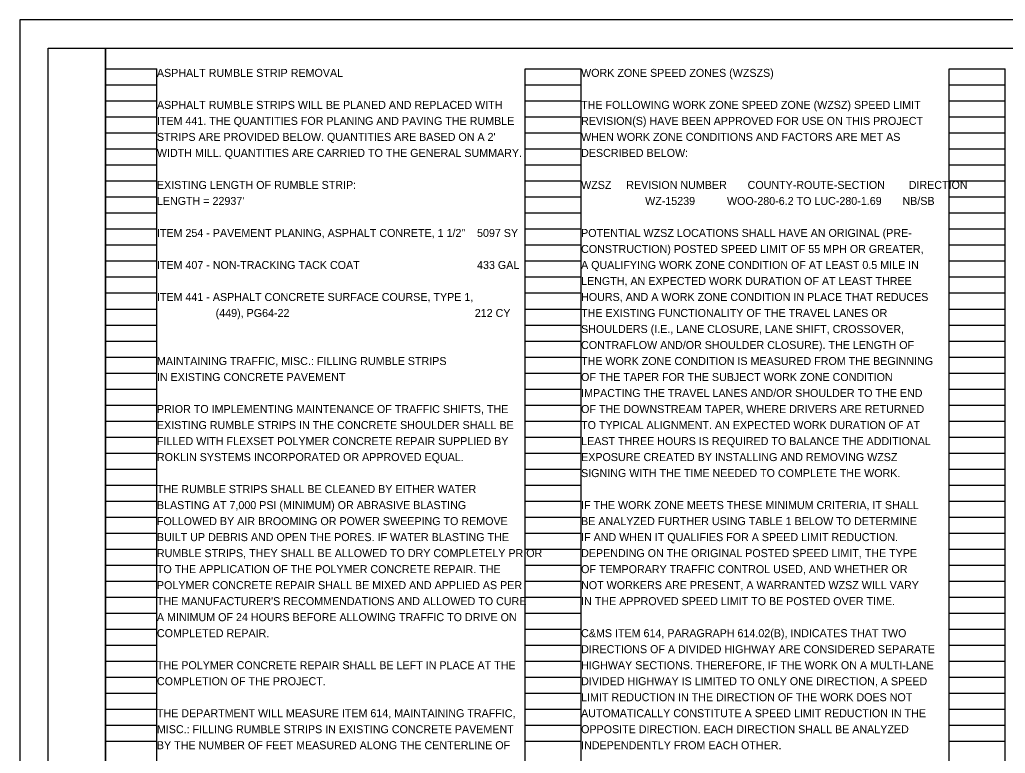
# Model space of a CAD drawing. Extents: x 0 to 34, y -3.9 to 22.
# Drawn here: x 0 to 17.24, y 9.17 to 22 of the extents above; entities that cross this region are included whole.
import ezdxf

# ---------------------------------------------------------------- set-up
doc = ezdxf.new("R2010")
doc.units = 0
for name, color, linetype in [('SH_Border', 7, 'Continuous'), ('SH_Cut_Line', 7, 'Continuous'), ('SH_Data', 7, 'Continuous'), ('SH_Text', 7, 'Continuous')]:
    doc.layers.add(name, color=color, linetype=linetype)

msp = doc.modelspace()

# ---------------------------------------------------------------- linework, layer by layer
at = {"layer": 'SH_Border'}
for points in [[(0.5, 21.5), (1.5, 21.5), (1.5, 0.5), (0.5, 0.5)], [(1.5, 21.5), (33.5, 21.5), (33.5, 0.5), (1.5, 0.5)]]:
    msp.add_lwpolyline(points, close=True, dxfattribs=at)
at = {"layer": 'SH_Cut_Line'}
msp.add_lwpolyline([(0, 0), (34, 0), (34, 22), (0, 22)], close=True, dxfattribs=at)
at = {"layer": 'SH_Data'}
for p, q in [((1.5, 0.98), (1.5, 21.14)), ((1.5, 21.14), (2.4, 21.14)), ((2.4, 0.98), (2.4, 21.14)), ((8.84, 0.98), (8.84, 21.14)), ((8.84, 21.14), (9.82, 21.14)), ((9.82, 0.98), (9.82, 21.14)), ((16.26, 0.98), (16.26, 21.14)), ((16.26, 21.14), (17.24, 21.14)), ((17.24, 0.98), (17.24, 21.14)), ((1.5, 20.86), (2.4, 20.86)), ((8.84, 20.86), (9.82, 20.86)), ((16.26, 20.86), (17.24, 20.86)), ((1.5, 20.58), (2.4, 20.58)), ((8.84, 20.58), (9.82, 20.58)), ((16.26, 20.58), (17.24, 20.58)), ((1.5, 20.3), (2.4, 20.3)), ((8.84, 20.3), (9.82, 20.3)), ((16.26, 20.3), (17.24, 20.3)), ((1.5, 20.02), (2.4, 20.02)), ((8.84, 20.02), (9.82, 20.02)), ((16.26, 20.02), (17.24, 20.02)), ((1.5, 19.74), (2.4, 19.74)), ((8.84, 19.74), (9.82, 19.74)), ((16.26, 19.74), (17.24, 19.74)), ((1.5, 19.46), (2.4, 19.46)), ((8.84, 19.46), (9.82, 19.46)), ((16.26, 19.46), (17.24, 19.46)), ((1.5, 19.18), (2.4, 19.18)), ((8.84, 19.18), (9.82, 19.18)), ((16.26, 19.18), (17.24, 19.18)), ((1.5, 18.9), (2.4, 18.9)), ((8.84, 18.9), (9.82, 18.9)), ((16.26, 18.9), (17.24, 18.9)), ((1.5, 18.62), (2.4, 18.62)), ((8.84, 18.62), (9.82, 18.62)), ((16.26, 18.62), (17.24, 18.62)), ((1.5, 18.34), (2.4, 18.34)), ((8.84, 18.34), (9.82, 18.34)), ((16.26, 18.34), (17.24, 18.34)), ((1.5, 18.06), (2.4, 18.06)), ((8.84, 18.06), (9.82, 18.06)), ((16.26, 18.06), (17.24, 18.06)), ((1.5, 17.78), (2.4, 17.78)), ((8.84, 17.78), (9.82, 17.78)), ((16.26, 17.78), (17.24, 17.78)), ((1.5, 17.5), (2.4, 17.5)), ((8.84, 17.5), (9.82, 17.5)), ((16.26, 17.5), (17.24, 17.5)), ((1.5, 17.22), (2.4, 17.22)), ((8.84, 17.22), (9.82, 17.22)), ((16.26, 17.22), (17.24, 17.22)), ((1.5, 16.94), (2.4, 16.94)), ((8.84, 16.94), (9.82, 16.94)), ((16.26, 16.94), (17.24, 16.94)), ((1.5, 16.66), (2.4, 16.66)), ((8.84, 16.66), (9.82, 16.66)), ((16.26, 16.66), (17.24, 16.66)), ((1.5, 16.38), (2.4, 16.38)), ((8.84, 16.38), (9.82, 16.38)), ((16.26, 16.38), (17.24, 16.38)), ((1.5, 16.1), (2.4, 16.1)), ((8.84, 16.1), (9.82, 16.1)), ((16.26, 16.1), (17.24, 16.1)), ((1.5, 15.82), (2.4, 15.82)), ((8.84, 15.82), (9.82, 15.82)), ((16.26, 15.82), (17.24, 15.82)), ((1.5, 15.54), (2.4, 15.54)), ((8.84, 15.54), (9.82, 15.54)), ((16.26, 15.54), (17.24, 15.54)), ((1.5, 15.26), (2.4, 15.26)), ((8.84, 15.26), (9.82, 15.26)), ((16.26, 15.26), (17.24, 15.26)), ((1.5, 14.98), (2.4, 14.98)), ((8.84, 14.98), (9.82, 14.98)), ((16.26, 14.98), (17.24, 14.98)), ((1.5, 14.7), (2.4, 14.7)), ((8.84, 14.7), (9.82, 14.7)), ((16.26, 14.7), (17.24, 14.7)), ((1.5, 14.42), (2.4, 14.42)), ((8.84, 14.42), (9.82, 14.42)), ((16.26, 14.42), (17.24, 14.42)), ((1.5, 14.14), (2.4, 14.14)), ((8.84, 14.14), (9.82, 14.14)), ((16.26, 14.14), (17.24, 14.14)), ((1.5, 13.86), (2.4, 13.86)), ((8.84, 13.86), (9.82, 13.86)), ((16.26, 13.86), (17.24, 13.86)), ((1.5, 13.58), (2.4, 13.58)), ((8.84, 13.58), (9.82, 13.58)), ((16.26, 13.58), (17.24, 13.58)), ((1.5, 13.3), (2.4, 13.3)), ((8.84, 13.3), (9.82, 13.3)), ((16.26, 13.3), (17.24, 13.3)), ((1.5, 13.02), (2.4, 13.02)), ((8.84, 13.02), (9.82, 13.02)), ((16.26, 13.02), (17.24, 13.02)), ((1.5, 12.74), (2.4, 12.74)), ((8.84, 12.74), (9.82, 12.74)), ((16.26, 12.74), (17.24, 12.74)), ((1.5, 12.46), (2.4, 12.46)), ((8.84, 12.46), (9.82, 12.46)), ((16.26, 12.46), (17.24, 12.46)), ((1.5, 12.18), (2.4, 12.18)), ((8.84, 12.18), (9.82, 12.18)), ((16.26, 12.18), (17.24, 12.18)), ((1.5, 11.9), (2.4, 11.9)), ((8.84, 11.9), (9.82, 11.9)), ((16.26, 11.9), (17.24, 11.9)), ((1.5, 11.62), (2.4, 11.62)), ((8.84, 11.62), (9.82, 11.62)), ((16.26, 11.62), (17.24, 11.62)), ((1.5, 11.34), (2.4, 11.34)), ((8.84, 11.34), (9.82, 11.34)), ((16.26, 11.34), (17.24, 11.34)), ((1.5, 11.06), (2.4, 11.06)), ((8.84, 11.06), (9.82, 11.06)), ((16.26, 11.06), (17.24, 11.06)), ((1.5, 10.78), (2.4, 10.78)), ((8.84, 10.78), (9.82, 10.78)), ((16.26, 10.78), (17.24, 10.78)), ((1.5, 10.5), (2.4, 10.5)), ((8.84, 10.5), (9.82, 10.5)), ((16.26, 10.5), (17.24, 10.5)), ((1.5, 10.22), (2.4, 10.22)), ((8.84, 10.22), (9.82, 10.22)), ((16.26, 10.22), (17.24, 10.22)), ((1.5, 9.94), (2.4, 9.94)), ((8.84, 9.94), (9.82, 9.94)), ((16.26, 9.94), (17.24, 9.94)), ((1.5, 9.66), (2.4, 9.66)), ((8.84, 9.66), (9.82, 9.66)), ((16.26, 9.66), (17.24, 9.66)), ((1.5, 9.38), (2.4, 9.38)), ((8.84, 9.38), (9.82, 9.38)), ((16.26, 9.38), (17.24, 9.38))]:
    msp.add_line(p, q, dxfattribs=at)

# ---------------------------------------------------------------- texts
at = {"layer": 'SH_Text'}
for s, p in [('ASPHALT RUMBLE STRIP REMOVAL', (2.4, 21)), ('WORK ZONE SPEED ZONES (WZSZS)', (9.82, 21)), ('ASPHALT RUMBLE STRIPS WILL BE PLANED AND REPLACED WITH', (2.4, 20.44)), ('THE FOLLOWING WORK ZONE SPEED ZONE (WZSZ) SPEED LIMIT', (9.82, 20.44)), ('ITEM 441. THE QUANTITIES FOR PLANING AND PAVING THE RUMBLE', (2.4, 20.16)), ('REVISION(S) HAVE BEEN APPROVED FOR USE ON THIS PROJECT', (9.82, 20.16)), ("STRIPS ARE PROVIDED BELOW. QUANTITIES ARE BASED ON A 2'", (2.4, 19.88)), ('WHEN WORK ZONE CONDITIONS AND FACTORS ARE MET AS', (9.82, 19.88)), ('WIDTH MILL. QUANTITIES ARE CARRIED TO THE GENERAL SUMMARY.', (2.4, 19.6)), ('DESCRIBED BELOW:', (9.82, 19.6)), ('EXISTING LENGTH OF RUMBLE STRIP:', (2.4, 19.04)), ('WZSZ     REVISION NUMBER       COUNTY-ROUTE-SECTION        DIRECTION', (9.82, 19.04)), ("LENGTH = 22937'", (2.4, 18.76)), ('WZ-15239', (10.94, 18.76)), ('      WOO-280-6.2 TO LUC-280-1.69       NB/SB', (12.06, 18.76)), ('ITEM 254 - PAVEMENT PLANING, ASPHALT CONRETE, 1 1/2"', (2.4, 18.2)), ('5097 SY', (8, 18.2)), ('POTENTIAL WZSZ LOCATIONS SHALL HAVE AN ORIGINAL (PRE-', (9.82, 18.2)), ('CONSTRUCTION) POSTED SPEED LIMIT OF 55 MPH OR GREATER,', (9.82, 17.92)), ('ITEM 407 - NON-TRACKING TACK COAT', (2.4, 17.64)), ('433 GAL', (8, 17.64)), ('A QUALIFYING WORK ZONE CONDITION OF AT LEAST 0.5 MILE IN', (9.82, 17.64)), ('LENGTH, AN EXPECTED WORK DURATION OF AT LEAST THREE', (9.82, 17.36)), ('ITEM 441 - ASPHALT CONCRETE SURFACE COURSE, TYPE 1,', (2.4, 17.08)), ('HOURS, AND A WORK ZONE CONDITION IN PLACE THAT REDUCES', (9.82, 17.08)), ('         (449), PG64-22', (2.96, 16.8)), ('          212 CY', (7.44, 16.8)), ('THE EXISTING FUNCTIONALITY OF THE TRAVEL LANES OR', (9.82, 16.8)), ('SHOULDERS (I.E., LANE CLOSURE, LANE SHIFT, CROSSOVER,', (9.82, 16.52)), ('CONTRAFLOW AND/OR SHOULDER CLOSURE). THE LENGTH OF', (9.82, 16.24)), ('MAINTAINING TRAFFIC, MISC.: FILLING RUMBLE STRIPS', (2.4, 15.96)), ('THE WORK ZONE CONDITION IS MEASURED FROM THE BEGINNING', (9.82, 15.96)), ('IN EXISTING CONCRETE PAVEMENT', (2.4, 15.68)), ('OF THE TAPER FOR THE SUBJECT WORK ZONE CONDITION', (9.82, 15.68)), ('IMPACTING THE TRAVEL LANES AND/OR SHOULDER TO THE END', (9.82, 15.4)), ('PRIOR TO IMPLEMENTING MAINTENANCE OF TRAFFIC SHIFTS, THE ', (2.4, 15.12)), ('OF THE DOWNSTREAM TAPER, WHERE DRIVERS ARE RETURNED', (9.82, 15.12)), ('EXISTING RUMBLE STRIPS IN THE CONCRETE SHOULDER SHALL BE', (2.4, 14.84)), ('TO TYPICAL ALIGNMENT. AN EXPECTED WORK DURATION OF AT', (9.82, 14.84)), ('FILLED WITH FLEXSET POLYMER CONCRETE REPAIR SUPPLIED BY', (2.4, 14.56)), ('LEAST THREE HOURS IS REQUIRED TO BALANCE THE ADDITIONAL', (9.82, 14.56)), ('ROKLIN SYSTEMS INCORPORATED OR APPROVED EQUAL.', (2.4, 14.28)), ('EXPOSURE CREATED BY INSTALLING AND REMOVING WZSZ', (9.82, 14.28)), ('SIGNING WITH THE TIME NEEDED TO COMPLETE THE WORK.', (9.82, 14)), ('THE RUMBLE STRIPS SHALL BE CLEANED BY EITHER WATER', (2.4, 13.72)), ('BLASTING AT 7,000 PSI (MINIMUM) OR ABRASIVE BLASTING', (2.4, 13.44)), ('IF THE WORK ZONE MEETS THESE MINIMUM CRITERIA, IT SHALL', (9.82, 13.44)), ('FOLLOWED BY AIR BROOMING OR POWER SWEEPING TO REMOVE', (2.4, 13.16)), ('BE ANALYZED FURTHER USING TABLE 1 BELOW TO DETERMINE', (9.82, 13.16)), ('BUILT UP DEBRIS AND OPEN THE PORES. IF WATER BLASTING THE', (2.4, 12.88)), ('IF AND WHEN IT QUALIFIES FOR A SPEED LIMIT REDUCTION.', (9.82, 12.88)), ('RUMBLE STRIPS, THEY SHALL BE ALLOWED TO DRY COMPLETELY PRIOR', (2.4, 12.6)), ('DEPENDING ON THE ORIGINAL POSTED SPEED LIMIT, THE TYPE', (9.82, 12.6)), ('TO THE APPLICATION OF THE POLYMER CONCRETE REPAIR. THE', (2.4, 12.32)), ('OF TEMPORARY TRAFFIC CONTROL USED, AND WHETHER OR', (9.82, 12.32)), ('POLYMER CONCRETE REPAIR SHALL BE MIXED AND APPLIED AS PER', (2.4, 12.04)), ('NOT WORKERS ARE PRESENT, A WARRANTED WZSZ WILL VARY', (9.82, 12.04)), ("THE MANUFACTURER'S RECOMMENDATIONS AND ALLOWED TO CURE", (2.4, 11.76)), ('IN THE APPROVED SPEED LIMIT TO BE POSTED OVER TIME.', (9.82, 11.76)), ('A MINIMUM OF 24 HOURS BEFORE ALLOWING TRAFFIC TO DRIVE ON', (2.4, 11.48)), ('COMPLETED REPAIR.', (2.4, 11.2)), ('C&MS ITEM 614, PARAGRAPH 614.02(B), INDICATES THAT TWO', (9.82, 11.2)), ('DIRECTIONS OF A DIVIDED HIGHWAY ARE CONSIDERED SEPARATE', (9.82, 10.92)), ('THE POLYMER CONCRETE REPAIR SHALL BE LEFT IN PLACE AT THE', (2.4, 10.64)), ('HIGHWAY SECTIONS. THEREFORE, IF THE WORK ON A MULTI-LANE', (9.82, 10.64)), ('COMPLETION OF THE PROJECT.', (2.4, 10.36)), ('DIVIDED HIGHWAY IS LIMITED TO ONLY ONE DIRECTION, A SPEED', (9.82, 10.36)), ('LIMIT REDUCTION IN THE DIRECTION OF THE WORK DOES NOT', (9.82, 10.08)), ('THE DEPARTMENT WILL MEASURE ITEM 614, MAINTAINING TRAFFIC,', (2.4, 9.8)), ('AUTOMATICALLY CONSTITUTE A SPEED LIMIT REDUCTION IN THE', (9.82, 9.8)), ('MISC.: FILLING RUMBLE STRIPS IN EXISTING CONCRETE PAVEMENT', (2.4, 9.52)), ('OPPOSITE DIRECTION. EACH DIRECTION SHALL BE ANALYZED', (9.82, 9.52)), ('BY THE NUMBER OF FEET MEASURED ALONG THE CENTERLINE OF', (2.4, 9.24)), ('INDEPENDENTLY FROM EACH OTHER.', (9.82, 9.24))]:
    msp.add_text(s, height=0.14, dxfattribs=at).set_placement(p)

doc.saveas('drawing.dxf')
